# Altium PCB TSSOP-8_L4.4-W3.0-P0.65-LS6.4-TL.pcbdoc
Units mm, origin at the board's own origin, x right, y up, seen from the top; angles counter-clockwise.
Board outline 20 x 15.93 mm, 2 copper layers (Top Layer, Bottom Layer), stack 0 mm thick; 1 components, 0 nets, 8 pads, 0 vias.
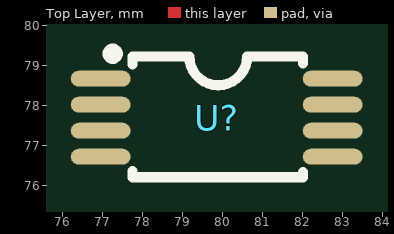
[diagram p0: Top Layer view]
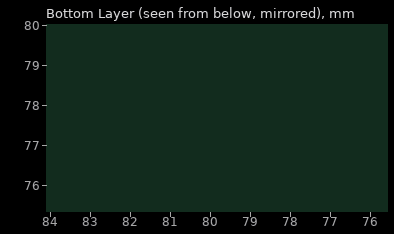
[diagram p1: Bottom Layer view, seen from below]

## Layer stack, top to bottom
Top Layer: signal copper (thickness not stored)
Bottom Layer: signal copper (thickness not stored)

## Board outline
89.85,69.85 69.85,69.85 69.85,85.777 89.85,85.777

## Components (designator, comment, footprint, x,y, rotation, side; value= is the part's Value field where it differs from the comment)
U? "" TSSOP-8_L4.4-W3.0-P0.65-LS6.4-TL 79.85,77.7 r0 top

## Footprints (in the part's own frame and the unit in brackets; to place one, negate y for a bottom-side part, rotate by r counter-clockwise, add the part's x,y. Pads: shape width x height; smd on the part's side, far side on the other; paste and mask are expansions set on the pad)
TSSOP-8_L4.4-W3.0-P0.65-LS6.4-TL [mm]
  oval 1.5x0.4 smd: 1(-2.9,0.975) 2(-2.9,0.325) 3(-2.9,-0.325) 4(-2.9,-0.975) 5(2.9,-0.975) 6(2.9,-0.325) 7(2.9,0.325) 8(2.9,0.975)
  silkscreen extent -2.73,-1.49 2.16,1.73

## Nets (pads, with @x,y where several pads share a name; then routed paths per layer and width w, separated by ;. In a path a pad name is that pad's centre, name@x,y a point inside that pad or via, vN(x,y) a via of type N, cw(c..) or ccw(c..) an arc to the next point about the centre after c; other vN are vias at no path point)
pads on no net: U?.1 U?.2 U?.3 U?.4 U?.5 U?.6 U?.7 U?.8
